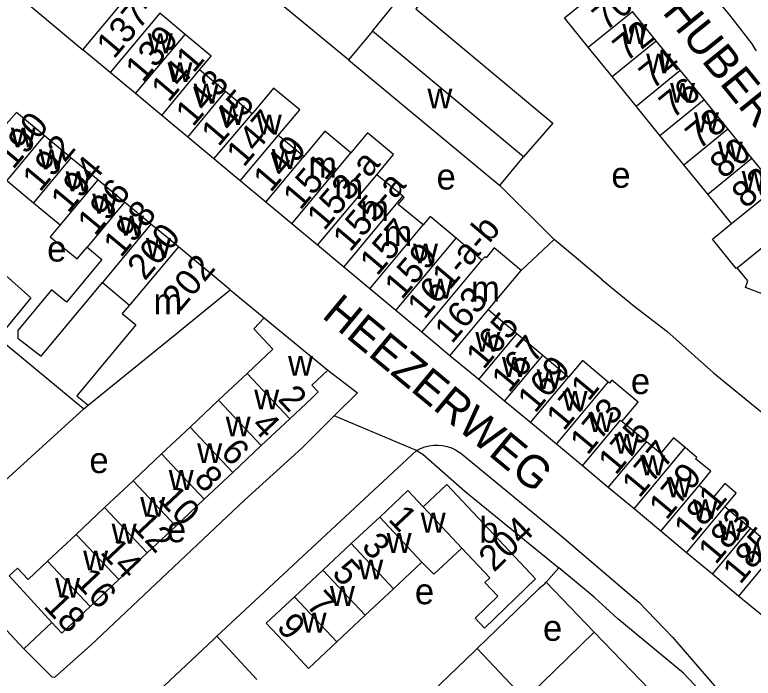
# Model space of a CAD drawing. Extents: x 161141 to 163125, y 381621 to 383200.
# Drawn here: x 162382.8 to 162497.1, y 381837.8 to 381940.5 of the extents above; entities that cross this region are included whole.
import ezdxf

# ---------------------------------------------------------------- set-up
doc = ezdxf.new("R2010")
doc.units = 0
for name, color, linetype in [('BLT_Basislijn', 7, 'Continuous'), ('BLT_Bebouwing', 7, 'Continuous'), ('BLT_Centroide', 7, 'Continuous'), ('BLT_Huisnummer', 7, 'Continuous'), ('BLT_Huisnummer_ tussenligend', 7, 'Continuous'), ('BLT_Huisnummer_reeks', 7, 'Continuous'), ('BLT_Onderverdeling_panden', 7, 'Continuous'), ('BLT_Straatnaam', 7, 'Continuous'), ('BLT_Vlakafsluiter', 7, 'Continuous')]:
    doc.layers.add(name, color=color, linetype=linetype)

msp = doc.modelspace()

# ---------------------------------------------------------------- linework, layer by layer
at = {"layer": 'BLT_Basislijn'}
for p, q in [((162438.16, 381937.97), (162449.18, 381951.54)), ((162434.46, 381933.53), (162420.24, 381945.27)), ((162466.26, 381905.7), (162457.86, 381914.05)), ((162461.16, 381900.93), (162466.26, 381905.7)), ((162416.18, 381897.9), (162421.42, 381893.59)), ((162393.52, 381879.51), (162394.2, 381880.06)), ((162374.2, 381861.92), (162393.52, 381879.51)), ((162444.99, 381873.03), (162414.1, 381844.29)), ((162465.07, 381852.68), (162467.02, 381854.86)), ((162464.75, 381852.32), (162465.07, 381852.68)), ((162472.45, 381844.9), (162465.07, 381852.68)), ((162414.1, 381844.29), (162420.31, 381837.61)), ((162461.81, 381834.53), (162454.36, 381842.38))]:
    msp.add_line(p, q, dxfattribs=at)
for points in [[(162453.43, 381951.99), (162444.91, 381941.4), (162466.08, 381923.71), (162461.56, 381918.49)], [(162497.57, 381934.92), (162497.4, 381935.1), (162496.93, 381936), (162493.3, 381940.62), (162491.66, 381942.59)], [(162375.96, 381905.04), (162385.32, 381896.67), (162380.22, 381890.46), (162393.52, 381879.51)], [(162473.72, 381899.48), (162478.6, 381895.42), (162483.73, 381891.53), (162490.91, 381885.04), (162501.06, 381876.83), (162501.39, 381876.64)], [(162431.26, 381885.48), (162435.85, 381881.97), (162432.25, 381878.39)], [(162384.27, 381842.35), (162388.57, 381837.99), (162389.04, 381837.96), (162394.57, 381842.85), (162418.45, 381865.4), (162427.23, 381873.42), (162432.25, 381878.39)], [(162444.99, 381873.03), (162445.61, 381873.36), (162446.27, 381873.6), (162446.95, 381873.78), (162447.64, 381873.87), (162448.34, 381873.89), (162449.03, 381873.82), (162449.72, 381873.68), (162450.38, 381873.46), (162451.02, 381873.16), (162451.61, 381872.79), (162451.86, 381872.61)], [(162444.99, 381873.03), (162445.96, 381872.47), (162452.46, 381866.73), (162467.02, 381854.86)], [(162451.86, 381872.61), (162467.34, 381859.82), (162479.4, 381849.56), (162484.61, 381844.16), (162491.45, 381836.22)], [(162488.94, 381835.49), (162488.88, 381835.83), (162486.28, 381838.55), (162476.14, 381846.96), (162472.45, 381850.34), (162467.02, 381854.86)], [(162464.75, 381852.32), (162463.9, 381851.62), (162460.41, 381848.21), (162454.36, 381842.38)], [(162373.17, 381806.36), (162400.66, 381832.19), (162405.95, 381836.6), (162413.57, 381843.79), (162414.1, 381844.29)], [(162434.07, 381822.85), (162453.97, 381842), (162454.36, 381842.38)]]:
    msp.add_lwpolyline(points, dxfattribs=at)
at = {"layer": 'BLT_Bebouwing'}
for p, q in [((162482.08, 381936.46), (162478.39, 381941.01)), ((162438.16, 381937.97), (162434.46, 381933.53)), ((162461.56, 381918.49), (162438.16, 381937.97)), ((162485.78, 381931.91), (162482.08, 381936.46)), ((162475.25, 381930.91), (162471.56, 381935.46)), ((162434.46, 381933.53), (162457.86, 381914.05)), ((162401.52, 381928.29), (162397.61, 381931.55)), ((162415.46, 381928.6), (162411.44, 381931.95)), ((162489.47, 381927.36), (162485.78, 381931.91)), ((162478.95, 381926.36), (162475.25, 381930.91)), ((162405.57, 381924.91), (162401.52, 381928.29)), ((162419.57, 381925.18), (162415.46, 381928.6)), ((162482.64, 381921.82), (162478.95, 381926.36)), ((162493.17, 381922.82), (162489.47, 381927.36)), ((162409.6, 381921.56), (162405.57, 381924.91)), ((162391.54, 381918.36), (162387.41, 381921.79)), ((162427.54, 381918.53), (162423.61, 381921.8)), ((162486.34, 381917.27), (162482.64, 381921.82)), ((162496.86, 381918.27), (162493.17, 381922.82)), ((162413.64, 381918.19), (162409.6, 381921.56)), ((162395.68, 381914.92), (162391.54, 381918.36)), ((162457.86, 381914.05), (162461.56, 381918.49)), ((162417.69, 381914.81), (162413.64, 381918.19)), ((162490.04, 381912.72), (162486.34, 381917.27)), ((162381.62, 381914.82), (162385.76, 381911.39)), ((162399.81, 381911.5), (162395.68, 381914.92)), ((162421.66, 381911.48), (162417.69, 381914.81)), ((162493.73, 381908.17), (162490.04, 381912.72)), ((162403.91, 381908.09), (162399.81, 381911.5)), ((162385.76, 381911.39), (162389.89, 381907.95)), ((162425.7, 381908.14), (162421.66, 381911.48)), ((162429.68, 381904.82), (162425.7, 381908.14)), ((162455.09, 381902.48), (162451.12, 381905.91)), ((162433.74, 381901.43), (162429.68, 381904.82)), ((162470.05, 381902.54), (162466.26, 381905.7)), ((162416.18, 381897.9), (162408.15, 381904.57)), ((162473.72, 381899.48), (162470.05, 381902.54)), ((162437.77, 381898.07), (162433.74, 381901.43)), ((162456.08, 381894.83), (162461.16, 381900.93)), ((162396.4, 381899.04), (162400.61, 381895.55)), ((162441.79, 381894.72), (162437.77, 381898.07)), ((162445.82, 381891.36), (162441.79, 381894.72)), ((162460.5, 381891.09), (162456.08, 381894.83)), ((162421.42, 381893.59), (162431.26, 381885.48)), ((162450.15, 381887.72), (162445.82, 381891.36)), ((162464.51, 381887.75), (162460.5, 381891.09)), ((162418.78, 381884.98), (162422.76, 381888.72)), ((162454.62, 381884.03), (162450.15, 381887.72)), ((162468.52, 381884.41), (162464.51, 381887.75)), ((162431.26, 381885.48), (162428.8, 381883.17)), ((162414.38, 381880.82), (162418.78, 381884.98)), ((162458.62, 381880.69), (162454.62, 381884.03)), ((162409.96, 381876.67), (162414.38, 381880.82)), ((162428.78, 381881.15), (162425.39, 381877.96)), ((162462.63, 381877.35), (162458.62, 381880.69)), ((162425.39, 381877.96), (162420.98, 381873.81)), ((162466.63, 381874.01), (162462.63, 381877.35)), ((162480.54, 381874.4), (162476.77, 381877.54)), ((162405.56, 381872.52), (162409.96, 381876.67)), ((162420.98, 381873.81), (162416.57, 381869.66)), ((162470.64, 381870.67), (162466.63, 381874.01)), ((162401.15, 381868.36), (162405.56, 381872.52)), ((162474.65, 381867.33), (162470.64, 381870.67)), ((162416.57, 381869.66), (162412.16, 381865.5)), ((162396.74, 381864.21), (162401.15, 381868.36)), ((162478.65, 381863.99), (162474.65, 381867.33)), ((162443.67, 381866.84), (162439.29, 381862.73)), ((162446.01, 381864.34), (162443.67, 381866.84)), ((162412.16, 381865.5), (162407.75, 381861.35)), ((162392.33, 381860.06), (162396.74, 381864.21)), ((162482.79, 381860.54), (162478.65, 381863.99)), ((162496.65, 381860.99), (162492.67, 381864.31)), ((162439.29, 381862.73), (162434.9, 381858.62)), ((162407.75, 381861.35), (162403.34, 381857.2)), ((162486.77, 381857.22), (162482.79, 381860.54)), ((162387.92, 381855.91), (162392.33, 381860.06)), ((162434.9, 381858.62), (162430.52, 381854.51)), ((162384.27, 381842.35), (162369.77, 381857.75)), ((162403.34, 381857.2), (162398.93, 381853.05)), ((162490.75, 381853.91), (162486.77, 381857.22)), ((162445.82, 381855.76), (162441.44, 381851.65)), ((162430.52, 381854.51), (162426.14, 381850.4)), ((162494.79, 381850.49), (162490.75, 381853.91)), ((162398.93, 381853.05), (162394.52, 381848.89)), ((162441.44, 381851.65), (162437.06, 381847.54)), ((162498.69, 381847.29), (162494.79, 381850.49)), ((162437.06, 381847.54), (162432.67, 381843.43)), ((162388.56, 381846.39), (162384.27, 381842.35)), ((162461.81, 381834.53), (162472.45, 381844.9))]:
    msp.add_line(p, q, dxfattribs=at)
for points in [[(162393.39, 381935.06), (162408.61, 381953.34)], [(162471.56, 381935.46), (162467.86, 381940.01), (162470.81, 381942.4), (162474.69, 381945.56)], [(162409.2, 381937.45), (162405.26, 381940.73)], [(162411.44, 381931.95), (162413.22, 381934.09), (162409.2, 381937.45)], [(162397.61, 381931.55), (162395.19, 381933.56), (162393.39, 381935.06)], [(162423.61, 381921.8), (162426.93, 381925.78), (162422.88, 381929.15), (162419.57, 381925.18)], [(162387.41, 381921.79), (162383.13, 381925.34), (162377.07, 381918.61)], [(162434.83, 381919.1), (162430.8, 381922.45), (162427.54, 381918.53)], [(162438.87, 381915.73), (162441.45, 381918.85), (162437.42, 381922.2), (162434.83, 381919.1)], [(162500.56, 381913.72), (162500, 381914.41), (162496.86, 381918.27)], [(162442.88, 381912.39), (162438.87, 381915.73)], [(162442.17, 381911.13), (162443.08, 381912.22), (162442.88, 381912.39)], [(162446, 381907.95), (162442.17, 381911.13)], [(162451.12, 381905.91), (162447.1, 381909.26), (162446, 381907.95)], [(162408.15, 381904.57), (162406.36, 381906.05), (162403.91, 381908.09)], [(162494.6, 381901.33), (162494.46, 381901.21), (162490.75, 381905.78), (162493.73, 381908.17)], [(162389.89, 381907.95), (162388.31, 381906.09), (162392.49, 381902.7), (162394.02, 381904.53)], [(162394.02, 381904.53), (162396.32, 381902.61), (162390.84, 381896.01), (162388.53, 381897.92), (162383.31, 381891.63), (162383.33, 381890.45), (162386.93, 381887.65), (162396.4, 381899.04)], [(162461.16, 381900.93), (162457, 381904.39), (162455.74, 381902.88), (162455.55, 381903.04), (162455.09, 381902.48)], [(162498.48, 381897.28), (162495.87, 381898.27), (162496.26, 381899.29), (162494.6, 381901.33)], [(162407.81, 381891.11), (162412.3, 381894.75), (162416.18, 381897.9)], [(162400.61, 381895.55), (162399.47, 381894.23), (162401.56, 381892.5), (162392.45, 381881.52), (162394.2, 381880.06)], [(162422.76, 381888.72), (162419.8, 381891.89), (162421.42, 381893.59)], [(162394.2, 381880.06), (162407.81, 381891.11)], [(162474.66, 381883.64), (162470.65, 381886.98), (162468.52, 381884.41)], [(162428.8, 381883.17), (162429.8, 381882.11), (162428.78, 381881.15)], [(162476.77, 381877.54), (162479.27, 381880.54), (162475.22, 381883.93), (162474.85, 381883.48), (162474.66, 381883.64)], [(162486.56, 381873.48), (162484.76, 381874.98), (162482.75, 381872.56), (162480.54, 381874.4)], [(162488.69, 381867.62), (162490.51, 381869.83), (162488.16, 381871.73), (162488.37, 381871.97), (162486.56, 381873.48)], [(162452.01, 381857.94), (162456.33, 381853.32), (162455.58, 381852.61), (162457.57, 381850.49), (162454.07, 381847.09), (162455.52, 381845.54), (162463.37, 381853.16), (162449.67, 381867.78), (162446.01, 381864.34)], [(162492.67, 381864.31), (162494.41, 381866.44), (162492.66, 381867.91), (162490.89, 381865.79), (162488.69, 381867.62)], [(162501.92, 381859.16), (162503.26, 381860.78), (162505.08, 381862.95), (162503.12, 381864.59), (162501.3, 381862.41), (162498.7, 381859.28), (162496.65, 381860.99)], [(162452.01, 381857.94), (162447.69, 381853.89), (162445.82, 381855.76)], [(162382, 381853.63), (162383.28, 381854.83), (162384.92, 381853.09), (162387.92, 381855.91)], [(162426.14, 381850.4), (162421.75, 381846.29), (162425.17, 381842.65), (162428.29, 381839.32), (162432.67, 381843.43)], [(162394.52, 381848.89), (162390.11, 381844.74), (162388.56, 381846.39)], [(162472.45, 381844.9), (162485.33, 381831.63), (162474.76, 381821.34)]]:
    msp.add_lwpolyline(points, dxfattribs=at)
at = {"layer": 'BLT_Onderverdeling_panden'}
for p, q in [((162405.26, 381940.73), (162397.61, 381931.55)), ((162471.56, 381935.46), (162478.39, 381941.01)), ((162401.52, 381928.29), (162409.2, 381937.45)), ((162475.25, 381930.91), (162482.08, 381936.46)), ((162405.57, 381924.91), (162411.44, 381931.95)), ((162478.95, 381926.36), (162485.78, 381931.91)), ((162409.6, 381921.56), (162415.46, 381928.6)), ((162482.64, 381921.82), (162489.47, 381927.36)), ((162413.64, 381918.19), (162419.57, 381925.18)), ((162387.41, 381921.79), (162381.62, 381914.82)), ((162417.69, 381914.81), (162423.61, 381921.8)), ((162486.34, 381917.27), (162493.17, 381922.82)), ((162391.54, 381918.36), (162385.76, 381911.39)), ((162421.66, 381911.48), (162427.54, 381918.53)), ((162425.7, 381908.14), (162434.83, 381919.1)), ((162490.04, 381912.72), (162496.86, 381918.27)), ((162429.68, 381904.82), (162438.87, 381915.73)), ((162395.68, 381914.92), (162389.89, 381907.95)), ((162493.73, 381908.17), (162500.56, 381913.72)), ((162399.81, 381911.5), (162394.02, 381904.53)), ((162433.74, 381901.43), (162442.88, 381912.39)), ((162403.91, 381908.09), (162396.4, 381899.04)), ((162494.6, 381901.33), (162504.26, 381909.17)), ((162437.77, 381898.07), (162446, 381907.95)), ((162445.82, 381891.36), (162455.09, 381902.48)), ((162441.79, 381894.72), (162447.67, 381901.76)), ((162450.15, 381887.72), (162456.08, 381894.83)), ((162454.62, 381884.03), (162460.5, 381891.09)), ((162458.62, 381880.69), (162464.51, 381887.75)), ((162425.39, 381877.96), (162418.78, 381884.98)), ((162462.63, 381877.35), (162468.52, 381884.41)), ((162466.63, 381874.01), (162474.66, 381883.64)), ((162420.98, 381873.81), (162414.38, 381880.82)), ((162416.57, 381869.66), (162409.96, 381876.67)), ((162474.65, 381867.33), (162480.54, 381874.4)), ((162478.65, 381863.99), (162486.56, 381873.48)), ((162412.16, 381865.5), (162405.56, 381872.52)), ((162407.75, 381861.35), (162401.15, 381868.36)), ((162482.79, 381860.54), (162488.69, 381867.62)), ((162403.34, 381857.2), (162396.74, 381864.21)), ((162452.01, 381857.94), (162446.01, 381864.34)), ((162486.77, 381857.22), (162492.67, 381864.31)), ((162445.82, 381855.76), (162439.29, 381862.73)), ((162490.75, 381853.91), (162496.65, 381860.99)), ((162398.93, 381853.05), (162392.33, 381860.06)), ((162501.92, 381859.16), (162494.79, 381850.49)), ((162441.44, 381851.65), (162434.9, 381858.62)), ((162394.52, 381848.89), (162387.92, 381855.91)), ((162437.06, 381847.54), (162430.52, 381854.51)), ((162382, 381853.63), (162388.56, 381846.39)), ((162432.67, 381843.43), (162426.14, 381850.4))]:
    msp.add_line(p, q, dxfattribs=at)
for points in [[(162447.67, 381901.76), (162451.12, 381905.91)], [(162408.15, 381904.57), (162400.61, 381895.55)], [(162470.64, 381870.67), (162476.54, 381877.74), (162476.77, 381877.54)]]:
    msp.add_lwpolyline(points, dxfattribs=at)
at = {"layer": 'BLT_Vlakafsluiter'}
for p, q in [((162384.22, 381942.78), (162393.39, 381935.06)), ((162444.99, 381873.03), (162432.25, 381878.39))]:
    msp.add_line(p, q, dxfattribs=at)

# ---------------------------------------------------------------- texts
at = {"layer": 'BLT_Centroide'}
for s, p in [('w', (162476.82, 381935.97)), ('w', (162403.42, 381934.53)), ('w', (162480.51, 381931.41)), ('w', (162406.47, 381930.08)), ('w', (162410.52, 381926.75)), ('w', (162484.21, 381926.88)), ('w', (162446.67, 381926)), ('w', (162414.58, 381923.42)), ('w', (162487.91, 381922.31)), ('w', (162420.28, 381921.95)), ('w', (162382.23, 381919.95)), ('w', (162491.6, 381917.78)), ('w', (162386.58, 381916.58)), ('w', (162422.61, 381916.62)), ('m', (162428.25, 381915.28)), ('w', (162390.72, 381913.16)), ('e', (162448.09, 381913.44)), ('e', (162475.13, 381913.71)), ('w', (162495.3, 381913.22)), ('m', (162432.28, 381911.97)), ('w', (162394.84, 381909.72)), ('m', (162436.28, 381908.56)), ('w', (162398.97, 381906.31)), ('m', (162439.88, 381904.69)), ('w', (162403.14, 381902.86)), ('e', (162387.86, 381902.29)), ('w', (162444.45, 381902)), ('w', (162446.75, 381896.56)), ('m', (162453.42, 381896.09)), ('m', (162404.31, 381894.12)), ('w', (162454.09, 381888.32)), ('w', (162425.11, 381884.61)), ('w', (162458.21, 381884.44)), ('w', (162463.56, 381882.55)), ('e', (162478.15, 381881.78)), ('w', (162419.88, 381879.39)), ('w', (162467.58, 381879.2)), ('w', (162471.58, 381875.88)), ('w', (162415.47, 381875.23)), ('w', (162475.59, 381872.53)), ('w', (162411.06, 381871.08)), ('e', (162394.39, 381869.55)), ('w', (162479.59, 381869.2)), ('w', (162406.66, 381866.94)), ('w', (162483.67, 381865.8)), ('w', (162402.25, 381862.78)), ('w', (162487.73, 381862.42)), ('w', (162445.64, 381860.33)), ('b', (162454.69, 381858.75)), ('w', (162397.83, 381858.62)), ('e', (162406.38, 381858.84)), ('w', (162491.7, 381859.11)), ('w', (162440.36, 381857.19)), ('w', (162495.69, 381855.72)), ('w', (162393.42, 381854.48)), ('w', (162435.98, 381853.08)), ('w', (162389.08, 381850.25)), ('e', (162444.74, 381849.24)), ('w', (162431.59, 381848.97)), ('w', (162427.22, 381844.86)), ('e', (162464.55, 381843.58))]:
    msp.add_text(s, height=4, dxfattribs=at).set_placement(p)
at = {"layer": 'BLT_Huisnummer'}
for s, rotation, p in [('70', 39.0951, (162474.24, 381937.86)), ('72', 39.0951, (162477.43, 381933.09)), ('141', 49.7186, (162406.63, 381926.79)), ('76', 39.0951, (162484.6, 381924.28)), ('145', 49.7159, (162414.38, 381919.93)), ('190', 50.2948, (162382.6, 381916.42)), ('149', 49.7159, (162422.42, 381912.84)), ('80', 39.0942, (162492.44, 381914.97)), ('194', 50.2953, (162391.12, 381909.64)), ('198', 50.2786, (162399.26, 381902.75)), ('157', 49.7164, (162438.9, 381899.93)), ('202', 50.2827, (162408.36, 381894.38)), ('165', 50.2223, (162455.36, 381885.42)), ('169', 50.2207, (162463.33, 381878.69)), ('2', 313.2791, (162423.4, 381880.89)), ('173', 50.2223, (162471.44, 381872.18)), ('6', 313.2793, (162414.52, 381872.6)), ('177', 50.2215, (162479.46, 381865.55)), ('10', 313.2837, (162404.84, 381865.41)), ('181', 50.2151, (162487.52, 381858.83)), ('1', 313.1516, (162440.46, 381862.32)), ('204', 44.1044, (162456.97, 381854.09)), ('185', 50.2151, (162495.06, 381852.18)), ('14', 313.2796, (162395.91, 381857.22)), ('5', 313.1516, (162431.76, 381853.94)), ('18', 313.2823, (162387.14, 381848.84)), ('9', 313.144, (162423.19, 381845.6))]:
    msp.add_text(s, height=4, rotation=rotation, dxfattribs=at).set_placement(p)
at = {"layer": 'BLT_Huisnummer_ tussenligend'}
for s, rotation, p in [('139', 49.7193, (162402.64, 381929.86)), ('74', 39.0951, (162481.49, 381928.82)), ('143', 49.7186, (162410.41, 381923.02)), ('147', 49.7181, (162418.26, 381916.76)), ('78', 39.0951, (162488.68, 381919.5)), ('192', 50.2948, (162386.75, 381912.91)), ('151', 49.7159, (162427.01, 381910.1)), ('82', 39.0942, (162495.82, 381910.37)), ('196', 50.2953, (162395.26, 381906.11)), ('200', 50.2786, (162402.98, 381899.2)), ('159', 49.7164, (162442.71, 381896.24)), ('163', 49.7145, (162450.46, 381889.42)), ('167', 50.2223, (162459.31, 381881.82)), ('171', 50.2207, (162467.77, 381875.94)), ('4', 313.2791, (162419.25, 381876.75)), ('175', 50.2223, (162475.81, 381869.09)), ('8', 313.2793, (162410.39, 381868.45)), ('179', 50.2215, (162483.65, 381862.13)), ('183', 50.2151, (162491.27, 381855.25)), ('12', 313.2837, (162400.72, 381861.26)), ('3', 313.1516, (162436.32, 381858.05)), ('16', 313.2796, (162391.93, 381852.61)), ('7', 313.1516, (162427.77, 381849.04))]:
    msp.add_text(s, height=4, rotation=rotation, dxfattribs=at).set_placement(p)
at = {"layer": 'BLT_Huisnummer_reeks'}
for s, rotation, p in [('137-a', 49.7193, (162398.17, 381933.51)), ('153-a', 49.7171, (162430.7, 381906.93)), ('155-a', 49.7171, (162434.72, 381903.63)), ('161-a-b', 49.7145, (162446.23, 381893.2))]:
    msp.add_text(s, height=4, rotation=rotation, dxfattribs=at).set_placement(p)
at = {"layer": 'BLT_Straatnaam'}
for s, rotation, p in [('ST HUBERTUSSTRAAT', 308.8959, (162476.37, 381948.96)), ('HEEZERWEG', 320.4062, (162430.18, 381893.74))]:
    msp.add_text(s, height=5, rotation=rotation, dxfattribs=at).set_placement(p)

doc.saveas('drawing.dxf')
